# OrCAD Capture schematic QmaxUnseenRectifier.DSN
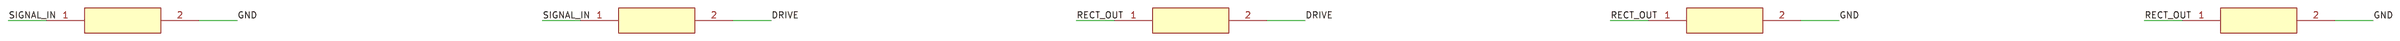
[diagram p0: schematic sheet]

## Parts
C1  100n
D1  1N4148
R1  1k
R2  100k
V1  dc=0 ampl=1 f=1k ac=1

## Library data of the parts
C1 = OBS_C1
D1 = OBS_D1
R1 = OBS_R1
R2 = OBS_R2
V1 = OBS_V1

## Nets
GND: C1.2 R2.2 V1.2
DRIVE: D1.2 R1.2
RECT_OUT: C1.1 D1.1 R2.1
SIGNAL_IN: R1.1 V1.1
